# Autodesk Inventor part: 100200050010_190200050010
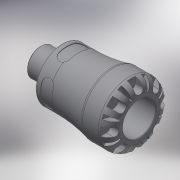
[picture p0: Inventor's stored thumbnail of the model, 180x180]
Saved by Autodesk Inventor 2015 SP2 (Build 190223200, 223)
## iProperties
Created: 2016-12
Part Number: 100200050010_190200050010
Material: Generic
Description: PLASSON MALE ADAPTOR 50X1" SERIES 1
Document SubType Name: Modeling
Designer: KIM
Mass: 447.839 g
Surface Area: 722.341 cm^2
Volume: 447.839 cm^3
Density: 1 g/cm^3
Appearance: Default
Author: KIM
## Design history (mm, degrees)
derived "1002.ipt"
feature "Solid1::1002.ipt"
tag "TaggingFeature1"
body "Solid1"
other parameters: "d0" = 125, "d1" = 32.76, "d3" = 62.5, "d4" = 85, "d6" = 78, "d8" = 72.25, "d13" = 9, "d14" = 9, "d15" = 0, "d17" = 360 deg, "d19" = 8 deg, "d20" = 1, "d21" = 1, "d22" = 8 deg, "d24" = 0, "d26" = 360 deg, "d32" = 0.925, "d33" = 8.5, "d34" = 33.249, "d35" = 12.5, "d38" = 19, "d39" = 0.99747, "d42" = 17.5, "d43" = 11.5, "d45" = 17.64, "d46" = 0, "d59" = 360 deg, "d61" = 14.875, "d62" = 1, "d64" = 0, "d65" = 0.85, "E_" = 85, "H_" = 125, "l_" = 78, "R_" = 33.249, "l_2" = 19, "d9" = 11.25, "d11" = 85, "d12" = 62.5
